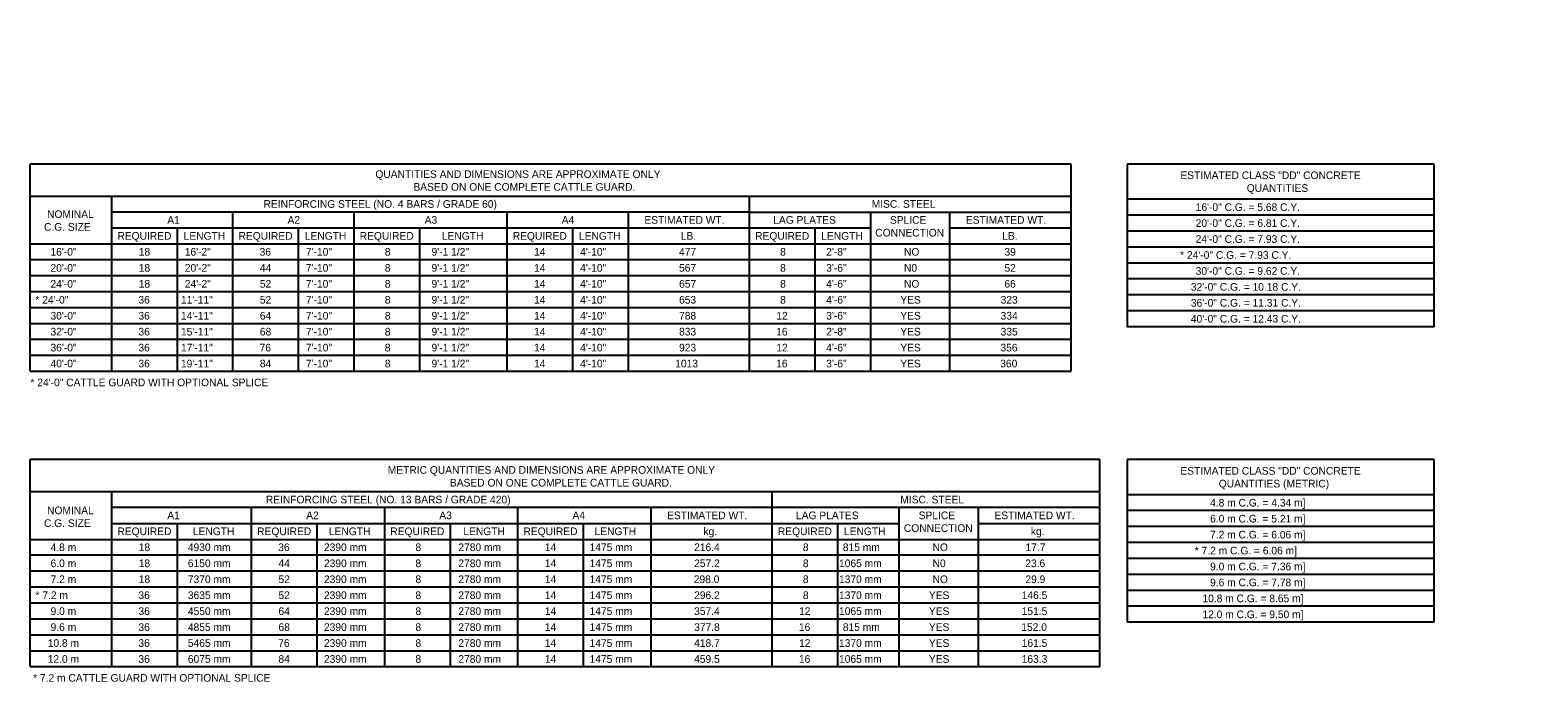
# Model space of a CAD drawing. Extents: x 49987.2 to 50044, y 49982.5 to 50011.4.
# Drawn here: x 49987.21 to 49999.02, y 49982.49 to 49987.6 of the extents above; entities that cross this region are included whole.
import ezdxf

# ---------------------------------------------------------------- set-up
doc = ezdxf.new("R2010")
doc.units = 0
doc.layers.add('Level 1', color=7, linetype='Continuous')
doc.layers.add('Level 2', color=7, linetype='Continuous')

msp = doc.modelspace()

# ---------------------------------------------------------------- linework, layer by layer
at = {"layer": 'Level 1'}
msp.add_line((49999.024, 49987.599), (49999.024, 49987.599), dxfattribs=at)
at = {"layer": 'Level 2'}
for p, q in [((49987.214, 49984.925), (49987.214, 49986.548)), ((49995.368, 49986.548), (49987.214, 49986.548)), ((49995.368, 49984.925), (49995.368, 49986.548)), ((49998.211, 49986.548), (49995.807, 49986.548)), ((49995.807, 49986.548), (49995.807, 49985.273)), ((49998.211, 49985.273), (49998.211, 49986.548)), ((49987.214, 49986.298), (49995.368, 49986.298)), ((49987.853, 49984.925), (49987.853, 49986.298)), ((49992.849, 49984.925), (49992.849, 49986.298)), ((49998.211, 49986.273), (49995.807, 49986.273)), ((49992.849, 49986.173), (49987.853, 49986.173)), ((49988.802, 49986.048), (49988.802, 49986.173)), ((49989.751, 49984.925), (49989.751, 49986.173)), ((49990.951, 49984.925), (49990.951, 49986.173)), ((49991.9, 49984.925), (49991.9, 49986.173)), ((49992.849, 49986.173), (49995.368, 49986.173)), ((49993.798, 49984.925), (49993.798, 49986.173)), ((49994.419, 49984.925), (49994.419, 49986.173)), ((49998.211, 49986.148), (49995.807, 49986.148)), ((49987.853, 49986.048), (49993.798, 49986.048)), ((49988.368, 49984.925), (49988.368, 49986.048)), ((49988.802, 49984.925), (49988.802, 49986.048)), ((49989.317, 49984.925), (49989.317, 49986.048)), ((49990.266, 49984.925), (49990.266, 49986.048)), ((49991.465, 49984.925), (49991.465, 49986.048)), ((49993.363, 49984.925), (49993.363, 49986.048)), ((49993.363, 49985.05), (49993.363, 49986.048)), ((49994.419, 49984.925), (49994.419, 49986.048)), ((49994.419, 49986.048), (49995.368, 49986.048)), ((49998.211, 49986.023), (49995.807, 49986.023)), ((49987.214, 49985.923), (49995.368, 49985.923)), ((49987.214, 49985.801), (49995.368, 49985.801)), ((49998.211, 49985.898), (49995.807, 49985.898)), ((49987.214, 49985.675), (49995.368, 49985.675)), ((49998.211, 49985.773), (49995.807, 49985.773)), ((49987.214, 49985.55), (49995.368, 49985.55)), ((49998.211, 49985.648), (49995.807, 49985.648)), ((49998.211, 49985.523), (49995.807, 49985.523)), ((49987.214, 49985.425), (49995.368, 49985.425)), ((49998.211, 49985.398), (49995.807, 49985.398)), ((49987.214, 49985.3), (49995.368, 49985.3)), ((49998.211, 49985.273), (49995.807, 49985.273)), ((49987.214, 49985.175), (49995.368, 49985.175)), ((49987.214, 49985.05), (49995.368, 49985.05)), ((49987.214, 49984.925), (49995.368, 49984.925)), ((49987.214, 49982.609), (49987.214, 49984.232)), ((49995.592, 49984.232), (49987.214, 49984.232)), ((49995.592, 49982.609), (49995.592, 49984.232)), ((49998.211, 49984.232), (49995.807, 49984.232)), ((49995.807, 49984.232), (49995.807, 49982.957)), ((49998.211, 49982.957), (49998.211, 49984.232)), ((49987.214, 49983.982), (49995.592, 49983.982)), ((49987.853, 49982.609), (49987.853, 49983.982)), ((49993.027, 49983.732), (49993.027, 49983.982)), ((49998.211, 49983.957), (49995.807, 49983.957)), ((49995.592, 49983.857), (49987.853, 49983.857)), ((49988.948, 49983.732), (49988.948, 49983.857)), ((49989.991, 49983.732), (49989.991, 49983.857)), ((49991.035, 49983.732), (49991.035, 49983.857)), ((49992.078, 49983.732), (49992.078, 49983.857)), ((49994.022, 49982.609), (49994.022, 49983.857)), ((49994.643, 49982.609), (49994.643, 49983.857)), ((49998.211, 49983.832), (49995.807, 49983.832)), ((49987.853, 49983.732), (49994.022, 49983.732)), ((49988.368, 49982.609), (49988.368, 49983.732)), ((49988.948, 49982.609), (49988.948, 49983.732)), ((49989.463, 49982.609), (49989.463, 49983.732)), ((49989.991, 49982.609), (49989.991, 49983.732)), ((49990.506, 49982.609), (49990.506, 49983.732)), ((49991.035, 49982.609), (49991.035, 49983.732)), ((49991.549, 49982.609), (49991.549, 49983.732)), ((49992.078, 49982.609), (49992.078, 49983.732)), ((49993.027, 49982.609), (49993.027, 49983.732)), ((49993.541, 49982.609), (49993.541, 49983.732)), ((49994.643, 49982.609), (49994.643, 49983.732)), ((49994.643, 49983.732), (49995.592, 49983.732)), ((49998.211, 49983.707), (49995.807, 49983.707)), ((49987.214, 49983.607), (49995.592, 49983.607)), ((49998.211, 49983.582), (49995.807, 49983.582)), ((49987.214, 49983.485), (49995.592, 49983.485)), ((49998.211, 49983.457), (49995.807, 49983.457)), ((49987.214, 49983.359), (49995.592, 49983.359)), ((49998.211, 49983.332), (49995.807, 49983.332)), ((49987.214, 49983.234), (49995.592, 49983.234)), ((49998.211, 49983.207), (49995.807, 49983.207)), ((49987.214, 49983.109), (49995.592, 49983.109)), ((49998.211, 49983.082), (49995.807, 49983.082)), ((49987.214, 49982.984), (49995.592, 49982.984)), ((49998.211, 49982.957), (49995.807, 49982.957)), ((49987.214, 49982.859), (49995.592, 49982.859)), ((49987.214, 49982.734), (49995.592, 49982.734)), ((49987.214, 49982.609), (49995.592, 49982.609))]:
    msp.add_line(p, q, dxfattribs=at)

# ---------------------------------------------------------------- texts
for s, p in [('QUANTITIES AND DIMENSIONS ARE APPROXIMATE ONLY', (49989.918, 49986.44)), ('BASED ON ONE COMPLETE CATTLE GUARD.', (49990.216, 49986.34)), ('ESTIMATED CLASS "DD" CONCRETE', (49996.224, 49986.431)), ('QUANTITIES', (49996.744, 49986.331)), ('REINFORCING STEEL (NO. 4 BARS / GRADE 60)', (49989.042, 49986.206)), ('MISC. STEEL', (49993.806, 49986.206)), ('NOMINAL', (49987.346, 49986.126)), ('A1', (49988.288, 49986.081)), ('A2', (49989.23, 49986.081)), ('A3', (49990.304, 49986.081)), ('A4', (49991.378, 49986.081)), ('ESTIMATED WT.', (49992.025, 49986.081)), ('LAG PLATES', (49993.035, 49986.081)), ('SPLICE', (49993.949, 49986.081)), ('ESTIMATED WT.', (49994.544, 49986.081)), ('16\'-0" C.G. = 5.68 C.Y.', (49996.344, 49986.181)), ('C.G. SIZE', (49987.322, 49986.026)), ('CONNECTION', (49993.834, 49985.981)), ('20\'-0" C.G. = 6.81 C.Y.', (49996.344, 49986.056)), ('REQUIRED', (49987.897, 49985.956)), ('LENGTH', (49988.416, 49985.956)), ('REQUIRED', (49988.846, 49985.956)), ('LENGTH', (49989.365, 49985.956)), ('REQUIRED', (49989.795, 49985.956)), ('LENGTH', (49990.439, 49985.956)), ('REQUIRED', (49990.994, 49985.956)), ('LENGTH', (49991.513, 49985.956)), ('LB.', (49992.31, 49985.956)), ('REQUIRED', (49992.893, 49985.956)), ('LENGTH', (49993.411, 49985.956)), ('LB.', (49994.829, 49985.956)), ('24\'-0" C.G. = 7.93 C.Y.', (49996.344, 49985.931)), ('16\'-0"', (49987.373, 49985.831)), ('18', (49988.064, 49985.831)), ('16\'-2"', (49988.425, 49985.831)), ('36', (49989.011, 49985.831)), ('7\'-10"', (49989.374, 49985.831)), ('8', (49989.992, 49985.831)), ('9\'-1 1/2"', (49990.358, 49985.831)), ('14', (49991.161, 49985.831)), ('4\'-10"', (49991.522, 49985.831)), ('477', (49992.297, 49985.831)), ('8', (49993.089, 49985.831)), ('2\'-8"', (49993.45, 49985.831)), ('NO', (49994.059, 49985.831)), ('39', (49994.846, 49985.831)), ('* 24\'-0" C.G. = 7.93 C.Y.', (49996.222, 49985.806)), ('20\'-0"', (49987.373, 49985.705)), ('18', (49988.064, 49985.705)), ('20\'-2"', (49988.425, 49985.705)), ('44', (49989.013, 49985.705)), ('7\'-10"', (49989.374, 49985.705)), ('8', (49989.992, 49985.705)), ('9\'-1 1/2"', (49990.358, 49985.705)), ('14', (49991.161, 49985.705)), ('4\'-10"', (49991.522, 49985.705)), ('567', (49992.297, 49985.705)), ('8', (49993.089, 49985.705)), ('3\'-6"', (49993.45, 49985.705)), ('N0', (49994.059, 49985.705)), ('52', (49994.846, 49985.705)), ('30\'-0" C.G. = 9.62 C.Y.', (49996.344, 49985.681)), ('24\'-0"', (49987.373, 49985.58)), ('18', (49988.064, 49985.58)), ('24\'-2"', (49988.425, 49985.58)), ('52', (49989.013, 49985.58)), ('7\'-10"', (49989.374, 49985.58)), ('8', (49989.992, 49985.58)), ('9\'-1 1/2"', (49990.358, 49985.58)), ('14', (49991.161, 49985.58)), ('4\'-10"', (49991.522, 49985.58)), ('657', (49992.297, 49985.58)), ('8', (49993.089, 49985.58)), ('4\'-6"', (49993.45, 49985.58)), ('NO', (49994.059, 49985.58)), ('66', (49994.845, 49985.58)), (' 32\'-0" C.G. = 10.18 C.Y.', (49996.284, 49985.556)), ('* 24\'-0"', (49987.255, 49985.455)), ('36', (49988.062, 49985.455)), ('11\'-11"', (49988.395, 49985.455)), ('52', (49989.013, 49985.455)), ('7\'-10"', (49989.374, 49985.455)), ('8', (49989.992, 49985.455)), ('9\'-1 1/2"', (49990.358, 49985.455)), ('14', (49991.161, 49985.455)), ('4\'-10"', (49991.522, 49985.455)), ('653', (49992.297, 49985.455)), ('8', (49993.089, 49985.455)), ('4\'-6"', (49993.45, 49985.455)), ('YES', (49994.03, 49985.455)), ('323', (49994.816, 49985.455)), (' 36\'-0" C.G. = 11.31 C.Y.', (49996.284, 49985.431)), ('30\'-0"', (49987.373, 49985.33)), ('36', (49988.062, 49985.33)), ('14\'-11"', (49988.395, 49985.33)), ('64', (49989.013, 49985.33)), ('7\'-10"', (49989.374, 49985.33)), ('8', (49989.992, 49985.33)), ('9\'-1 1/2"', (49990.358, 49985.33)), ('14', (49991.161, 49985.33)), ('4\'-10"', (49991.522, 49985.33)), ('788', (49992.297, 49985.33)), ('12', (49993.059, 49985.33)), ('3\'-6"', (49993.45, 49985.33)), ('YES', (49994.03, 49985.33)), ('334', (49994.816, 49985.33)), (' 40\'-0" C.G. = 12.43 C.Y.', (49996.284, 49985.306)), ('32\'-0"', (49987.373, 49985.205)), ('36', (49988.062, 49985.205)), ('15\'-11"', (49988.395, 49985.205)), ('68', (49989.013, 49985.205)), ('7\'-10"', (49989.374, 49985.205)), ('8', (49989.992, 49985.205)), ('9\'-1 1/2"', (49990.358, 49985.205)), ('14', (49991.161, 49985.205)), ('4\'-10"', (49991.522, 49985.205)), ('833', (49992.297, 49985.205)), ('16', (49993.058, 49985.205)), ('2\'-8"', (49993.45, 49985.205)), ('YES', (49994.03, 49985.205)), ('335', (49994.816, 49985.205)), ('36\'-0"', (49987.373, 49985.08)), ('36', (49988.062, 49985.08)), ('17\'-11"', (49988.395, 49985.08)), ('76', (49989.011, 49985.08)), ('7\'-10"', (49989.374, 49985.08)), ('8', (49989.992, 49985.08)), ('9\'-1 1/2"', (49990.358, 49985.08)), ('14', (49991.161, 49985.08)), ('4\'-10"', (49991.522, 49985.08)), ('923', (49992.297, 49985.08)), ('12', (49993.059, 49985.08)), ('4\'-6"', (49993.45, 49985.08)), ('YES', (49994.03, 49985.08)), ('356', (49994.815, 49985.08)), ('40\'-0"', (49987.373, 49984.955)), ('36', (49988.062, 49984.955)), ('19\'-11"', (49988.395, 49984.955)), ('84', (49989.013, 49984.955)), ('7\'-10"', (49989.374, 49984.955)), ('8', (49989.992, 49984.955)), ('9\'-1 1/2"', (49990.358, 49984.955)), ('14', (49991.161, 49984.955)), ('4\'-10"', (49991.522, 49984.955)), ('1013', (49992.267, 49984.955)), ('16', (49993.058, 49984.955)), ('3\'-6"', (49993.45, 49984.955)), ('YES', (49994.03, 49984.955)), ('360', (49994.813, 49984.955)), ('* 24\'-0" CATTLE GUARD WITH OPTIONAL SPLICE', (49987.216, 49984.807)), ('METRIC QUANTITIES AND DIMENSIONS ARE APPROXIMATE ONLY', (49990.015, 49984.121)), ('ESTIMATED CLASS "DD" CONCRETE', (49996.224, 49984.114)), ('BASED ON ONE COMPLETE CATTLE GUARD.', (49990.502, 49984.021)), ('QUANTITIES (METRIC)', (49996.525, 49984.014)), ('REINFORCING STEEL (NO. 13 BARS / GRADE 420)', (49989.06, 49983.889)), ('MISC. STEEL', (49994.03, 49983.889)), ('4.8 m C.G. = 4.34 m]', (49996.457, 49983.864)), ('NOMINAL', (49987.346, 49983.804)), ('A1', (49988.288, 49983.765)), ('A2', (49989.376, 49983.765)), ('A3', (49990.419, 49983.765)), ('A4', (49991.462, 49983.765)), ('ESTIMATED WT.', (49992.203, 49983.765)), ('LAG PLATES', (49993.213, 49983.765)), ('SPLICE', (49994.174, 49983.765)), ('ESTIMATED WT.', (49994.768, 49983.765)), ('6.0 m C.G. = 5.21 m]', (49996.457, 49983.739)), ('C.G. SIZE', (49987.322, 49983.704)), ('REQUIRED', (49987.897, 49983.64)), ('LENGTH', (49988.488, 49983.64)), ('REQUIRED', (49988.992, 49983.64)), ('LENGTH', (49989.554, 49983.64)), ('REQUIRED', (49990.035, 49983.64)), ('LENGTH', (49990.607, 49983.64)), ('REQUIRED', (49991.078, 49983.64)), ('LENGTH', (49991.635, 49983.64)), ('kg.', (49992.488, 49983.64)), ('REQUIRED', (49993.071, 49983.64)), ('LENGTH', (49993.589, 49983.64)), ('CONNECTION', (49994.058, 49983.665)), ('kg.', (49995.053, 49983.64)), ('7.2 m C.G. = 6.06 m]', (49996.457, 49983.614)), ('  4.8 m', (49987.329, 49983.515)), ('18', (49988.064, 49983.515)), ('4930 mm', (49988.449, 49983.515)), ('36', (49989.157, 49983.515)), ('2390 mm', (49989.515, 49983.515)), ('8', (49990.232, 49983.515)), ('2780 mm', (49990.568, 49983.515)), ('14', (49991.245, 49983.515)), ('1475 mm', (49991.596, 49983.515)), ('216.4', (49992.415, 49983.515)), ('8', (49993.267, 49983.515)), ('815 mm', (49993.58, 49983.515)), ('NO', (49994.283, 49983.515)), ('17.7', (49995.011, 49983.515)), ('* 7.2 m C.G. = 6.06 m]', (49996.337, 49983.489)), ('  6.0 m', (49987.329, 49983.389)), ('18', (49988.064, 49983.389)), ('6150 mm', (49988.449, 49983.389)), ('44', (49989.159, 49983.389)), ('2390 mm', (49989.515, 49983.389)), ('8', (49990.232, 49983.389)), ('2780 mm', (49990.568, 49983.389)), ('14', (49991.245, 49983.389)), ('1475 mm', (49991.596, 49983.389)), ('257.2', (49992.415, 49983.389)), ('8', (49993.267, 49983.389)), ('1065 mm', (49993.55, 49983.389)), ('N0', (49994.283, 49983.389)), ('23.6', (49995.009, 49983.389)), ('9.0 m C.G. = 7.36 m]', (49996.457, 49983.364)), ('  7.2 m', (49987.329, 49983.264)), ('18', (49988.064, 49983.264)), ('7370 mm', (49988.449, 49983.264)), ('52', (49989.159, 49983.264)), ('2390 mm', (49989.515, 49983.264)), ('8', (49990.232, 49983.264)), ('2780 mm', (49990.568, 49983.264)), ('14', (49991.245, 49983.264)), ('1475 mm', (49991.596, 49983.264)), ('298.0', (49992.412, 49983.264)), ('8', (49993.267, 49983.264)), ('1370 mm', (49993.55, 49983.264)), ('NO', (49994.283, 49983.264)), ('29.9', (49995.01, 49983.264)), ('  * 7.2 m', (49987.211, 49983.139)), ('36', (49988.062, 49983.139)), ('3635 mm', (49988.449, 49983.139)), ('52', (49989.159, 49983.139)), ('2390 mm', (49989.515, 49983.139)), ('8', (49990.232, 49983.139)), ('2780 mm', (49990.568, 49983.139)), ('14', (49991.245, 49983.139)), ('1475 mm', (49991.596, 49983.139)), ('296.2', (49992.415, 49983.139)), ('8', (49993.267, 49983.139)), ('1370 mm', (49993.55, 49983.139)), ('YES', (49994.254, 49983.139)), ('146.5', (49994.981, 49983.139)), ('9.6 m C.G. = 7.78 m]', (49996.457, 49983.239)), ('  9.0 m', (49987.329, 49983.014)), ('36', (49988.062, 49983.014)), ('4550 mm', (49988.449, 49983.014)), ('64', (49989.159, 49983.014)), ('2390 mm', (49989.515, 49983.014)), ('8', (49990.232, 49983.014)), ('2780 mm', (49990.568, 49983.014)), ('14', (49991.245, 49983.014)), ('1475 mm', (49991.596, 49983.014)), ('357.4', (49992.415, 49983.014)), ('12', (49993.237, 49983.014)), ('1065 mm', (49993.55, 49983.014)), ('YES', (49994.254, 49983.014)), ('151.5', (49994.981, 49983.014)), ('10.8 m C.G. = 8.65 m]', (49996.397, 49983.114)), ('  9.6 m', (49987.329, 49982.889)), ('36', (49988.062, 49982.889)), ('4855 mm', (49988.449, 49982.889)), ('68', (49989.159, 49982.889)), ('2390 mm', (49989.515, 49982.889)), ('8', (49990.232, 49982.889)), ('2780 mm', (49990.568, 49982.889)), ('377.8', (49992.415, 49982.889)), ('16', (49993.236, 49982.889)), ('815 mm', (49993.58, 49982.889)), ('YES', (49994.254, 49982.889)), ('152.0', (49994.978, 49982.889)), ('12.0 m C.G. = 9.50 m]', (49996.397, 49982.989)), ('14', (49991.245, 49982.889)), ('1475 mm', (49991.596, 49982.889)), (' 10.8 m', (49987.329, 49982.764)), ('36', (49988.062, 49982.764)), ('5465 mm', (49988.449, 49982.764)), ('76', (49989.157, 49982.764)), ('2390 mm', (49989.515, 49982.764)), ('8', (49990.232, 49982.764)), ('2780 mm', (49990.568, 49982.764)), ('14', (49991.245, 49982.764)), ('1475 mm', (49991.596, 49982.764)), ('418.7', (49992.415, 49982.764)), ('12', (49993.237, 49982.764)), ('1370 mm', (49993.55, 49982.764)), ('YES', (49994.254, 49982.764)), ('161.5', (49994.981, 49982.764)), (' 12.0 m', (49987.329, 49982.639)), ('36', (49988.062, 49982.639)), ('6075 mm', (49988.449, 49982.639)), ('84', (49989.159, 49982.639)), ('2390 mm', (49989.515, 49982.639)), ('8', (49990.232, 49982.639)), ('2780 mm', (49990.568, 49982.639)), ('14', (49991.245, 49982.639)), ('1475 mm', (49991.596, 49982.639)), ('459.5', (49992.415, 49982.639)), ('16', (49993.236, 49982.639)), ('1065 mm', (49993.55, 49982.639)), ('YES', (49994.254, 49982.639)), ('163.3', (49994.981, 49982.639)), ('* 7.2 m CATTLE GUARD WITH OPTIONAL SPLICE', (49987.237, 49982.491))]:
    msp.add_text(s, height=0.06, dxfattribs=at).set_placement(p)

doc.saveas('drawing.dxf')
